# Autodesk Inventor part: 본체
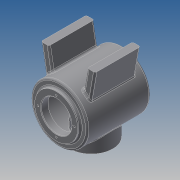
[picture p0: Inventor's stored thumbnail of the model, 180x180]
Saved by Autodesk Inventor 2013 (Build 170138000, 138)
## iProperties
Created: 2015-01
Part Number: 본체
Material: Generic
Document SubType Name: Modeling
Designer: kb54323
Density: 1 g/cm^3
Author: kb54323
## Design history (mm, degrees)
sketch "스케치1"
  geometry: C1 r 50 at (0, 0); 1 further point
  constraints: 1 centre point, 1 coincident
  dimensions: "d0" = 100 diameter of C1
extrude "돌출1" new body sketch "스케치1" distance "d2" = 112; taper "d3" = 0 deg
sketch "스케치2"
  geometry: C1 r 50 at (0, 0) reference; C2 r 38 at (0, 0)
  constraints: 1 centre point, 1 coincident
  dimensions: "d4" = 76 diameter of C2
extrude "돌출2" join sketch "스케치2" distance "d6" = 5; taper "d7" = 0 deg
node "작업 평면1"
sketch "스케치3"
  geometry: L1 (38, 117)-(-38, 117) reference; L2 (38, -5)-(-38, -5) reference; L3 (27, 117)-(27, 104.5); L4 (50, 112)-(-50, 112) reference; L5 (27, 104.5)-(45, 104.5); L6 (45, 104.5)-(45, 7.5); L7 (45, 7.5)-(27, 7.5); L8 (27, 7.5)-(27, -5); L9 (0, 117)-(0, -5); 1 further point
  constraints: 12 end point, 3 collinear, 2 midpoint, 2 parallel, 2 perpendicular, 2 point on line
  dimensions: "d8" = 54 diameter of L3 L9; "d10" = 90 diameter of L6 L9; "d11" = 97 distance of L5.end L6.end
revolve "회전1" sketch "스케치3" stored, may be unused: angle "d12" = 90 deg
sketch "스케치5"
  geometry: L1 (-39.336, -30.865)-(-48, -80); L2 (-48, -80)-(-34, -80); L3 (-34, -80)-(-27.282, -41.901); A1 r 50 centre (0, 0) between (-39.336, -30.865) and (-27.282, -41.901) reference; A2 r 50 centre (0, 0) between (-39.336, -30.865) and (-27.282, -41.901); 1 further point
  constraints: 6 end point, 4 point on circle, 1 centre point, 1 coincident, 1 concentric, 1 horizontal, 1 parallel
  dimensions: "d14" = 100 deg angle of L2 L1; "d15" = 14 distance of L1.end L2.end; "d17" = 48 horizontal distance of L1.end point (0, 0); "d19" = 80 distance from line of L2 point (0, 0)
extrude "돌출3" join sketch "스케치5" stored distance "d20" = 80; taper "d21" = 0 deg
node "작업 평면3"
sketch "스케치6"
  geometry: L1 (86, -101)-(10, -101) reference; C1 r 38 at (48, -39); 1 further point
  constraints: 1 centre point, 1 vertical alignment
  dimensions: "d23" = 76 diameter of C1; "d25" = 62 distance from line of C1.centre L1
extrude "돌출4" join sketch "스케치6" stored distance "d26" = 80; taper "d27" = 0 deg
sketch "스케치7"
  geometry: C1 r 38 at (0, 0) reference; C2 r 27 at (0, 0); 1 further point
  constraints: 1 centre point, 1 coincident
  dimensions: "d28" = 54 diameter of C2
extrude "돌출5" cut sketch "스케치7" stored distance "d30" = 30; taper "d31" = 0 deg
sketch "스케치8"
  geometry: C1 r 27 at (0, 0) reference; 2 further points
  constraints: 1 vertical alignment
  dimensions: "d32" = 32 distance of C1.centre point (0, 32)
hole "구멍1" sketch "스케치8" at (0, 32) diameter "d33" = 3.242; stored, may be unused: countersink angle "d37" = 90 deg, drill point angle "d39" = 118 deg; dims "d34" = 8, "d35" = 4, "d36" = 2, "d38" = 10
sketch "스케치9"
  geometry: C1 r 27 at (0, 0) reference; 1 further point
  constraints: 1 vertical alignment
  dimensions: "d43" = 32 distance of C1.centre point (0, 32)
hole "구멍2" sketch "스케치9" at (0, 32) diameter "d44" = 3.242; stored, may be unused: countersink angle "d48" = 90 deg, drill point angle "d50" = 118 deg; dims "d45" = 8, "d46" = 4, "d47" = 2, "d49" = 10
node "작업 평면5"
  node "작업 평면4"
sketch "스케치11"
  geometry: L1 (30, 6)-(84, 6); L2 (84, 6)-(84, -6); L3 (84, -6)-(30, -6); L4 (30, -6)-(30, 6); L5 (-5, -38)-(-5, 38) reference; 2 further points
  constraints: 8 end point, 2 parallel, 1 horizontal, 1 horizontal alignment, 1 midpoint, 1 perpendicular
  dimensions: "d55" = 54 distance of L1.start L1.end; "d57" = 12 distance of L3.end L1.start; "d59" = 35 distance between parallel lines of L4 L5
extrude "돌출6" join sketch "스케치11" stored distance "d60" = 80; taper "d61" = 0 deg
sketch "스케치12"
  geometry: L1 (38, -5)-(-38, -5) reference; 2 further points
  constraints: 1 vertical alignment, 1 other
  dimensions: "d62" = 62 distance from line of point (0, 57) L1
feature "엠보싱1" sketch "스케치12" dims "d63" = 0.5, "d64" = 0
fillet "모깎기1" dims "d65" = 3, "d66" = 3
fillet "모깎기2" dims "d67" = 3
chamfer "모따기1" distance "d68" = 1; stored, may be unused: second distance "d69" = 2, angle "d70" = 45 deg
chamfer "모따기2" distance "d71" = 1; stored, may be unused: second distance "d72" = 2, angle "d73" = 45 deg
node "솔리드1"
mirror "대칭1"
mirror "대칭2"
pattern_circular "원형 패턴1" dims angle "d41" = 360 deg
pattern_circular "원형 패턴2" dims angle "d52" = 360 deg
mirror "대칭3"
other parameters: "d22" = -142, "d54" = -2
